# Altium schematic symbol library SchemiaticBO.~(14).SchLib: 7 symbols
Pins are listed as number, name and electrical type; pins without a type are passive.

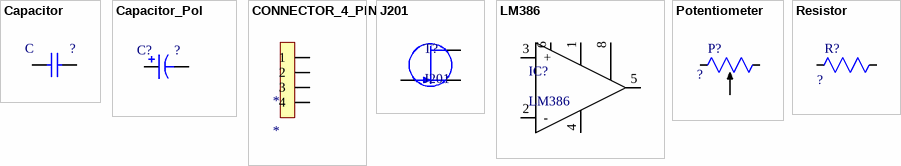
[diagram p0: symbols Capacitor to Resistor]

## Capacitor
designator C  (value not drawn)
footprint SMD_0603_BO
footprint SMD_1206_BO
pins: 1, 2

## Capacitor_Pol
designator C?  (value not drawn)
footprint PANASONIC_B_BO
footprint PANASONIC_C_BO
footprint PANASONIC_D8_BO
pins: 1, 2

## CONNECTOR_4_PIN
designator *
footprint Connector double
pins: 1, 2, 3, 4

## J201
designator T?
footprint SOT23_BO
pins: 1 D, 2 S, G 3

## LM386
designator IC?
footprint SO8_BO
pins: 1, 2 -, 3 +, 4, 5, 6, 8

## Potentiometer
designator P?  (value not drawn)
footprint POT_1801-J_BO
pins: 1, 2, 3

## Resistor
designator R?  (value not drawn)
footprint SMD_1206_BO
pins: 1 OUT, 2 OUT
